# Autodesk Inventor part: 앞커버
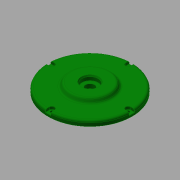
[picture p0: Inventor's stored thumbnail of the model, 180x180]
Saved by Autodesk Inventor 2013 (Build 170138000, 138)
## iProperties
Created: 2016-11
Part Number: 앞커버
Material: 일반
Document SubType Name: Modeling
Designer: mduedu
Density: 2.71 g/cm^3
Mass: 511.35 g
Surface Area: 365.029 cm^2
Volume: 188.69 cm^3
Author: mduedu
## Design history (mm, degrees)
sketch "스케치1"
  geometry: L1 (22, -12.5)-(22, -30); L2 (22, -30)-(16, -33.464); L3 (16, -33.464)-(16, -65); L4 (16, -65)-(8, -65); L5 (8, -65)-(8, -53); L6 (8, -53)-(0, -53); L7 (0, -53)-(0, -14); L8 (0, 0)-(22, 0); L9 (8, -14)-(8, -7); L10 (8, -7)-(14.5, -7); L11 (14.5, -7)-(14.5, -12.5); L12 (0, -14)-(8, -14); L13 (14.5, -12.5)-(22, -12.5)
  constraints: 26 end point, 8 parallel, 3 perpendicular, 2 horizontal, 2 vertical alignment, 1 collinear
  dimensions: "d0" = 8 distance of L5.end L6.end; "d2" = 8 distance of L3.end L4.end; "d3" = 6 distance between parallel lines of L1 L3; "d4" = 120 deg angle of L3 L2; "d5" = 7.5 distance of L11.end L1.start; "d6" = 60 diameter of L1.end L8; "d7" = 14 diameter of L10 L8; "d8" = 28 diameter of L12 L8; "d9" = 25 diameter of L13 L8; "d10" = 106 diameter of L6 L8; "d11" = 130 diameter of L4 L8
revolve "회전1" sketch "스케치1" stored, may be unused: angle "d12" = 90 deg
fillet "모깎기1" dims "d13" = 0.3
fillet "모깎기2" dims "d14" = 3
chamfer "모따기1" distance "d15" = 1; stored, may be unused: second distance "d16" = 2, angle "d17" = 45 deg
fillet "모깎기3" dims "d18" = 0.3
chamfer "모따기2" distance "d36" = 2; stored, may be unused: second distance "d37" = 2, angle "d38" = 30 deg
sketch "스케치3"
  geometry: C1 r 65 at (0, 0) reference; A1 r 59 centre (0, 0) between (0, 59) and (59, 0); 2 further points
  constraints: 4 point on circle, 2 horizontal alignment, 2 vertical alignment, 1 centre point, 1 coincident
  dimensions: "d33" = 118 diameter of A1
sketch "스케치4"
  geometry: 4 further points
  constraints: 4 other
hole "구멍2" sketch "스케치4" at (0, 59), (-59, 0), (59, 0), (0, -59) diameter "d39" = 4.5; stored, may be unused: countersink angle "d43" = 90 deg, drill point angle "d45" = 0 deg; dims "d40" = 6, "d41" = 8, "d42" = 4.6, "d44" = 8
sketch "스케치6"
  geometry: L1 (-4, 5.877)-(-4, 0); L2 (4, 5.877)-(4, 0); A1 r 4 centre (0, 0) between (-2.712, 2.941) and (2.712, 2.941) reference; A2 r 65 centre (0, -59) between (-4, 5.877) and (4, 5.877) reference; 1 further point
  constraints: 4 end point, 4 point on circle, 2 tangent, 2 vertical
extrude "돌출2" cut sketch "스케치6" stored distance "d51" = 10; taper "d52" = 0 deg
fillet "모깎기5" dims "d56" = 0.3
fillet "모깎기6" dims "d57" = 0.3
sketch "스케치5"
  geometry: C1 r 22 at (0, 0); C2 r 45 at (0, 0); 1 further point
  constraints: 2 centre point, 2 coincident
  dimensions: "d46" = 44 diameter of C1; "d47" = 90 diameter of C2
extrude "돌출1" cut sketch "스케치5" distance "d48" = 8; taper "d49" = 0 deg
fillet "모깎기4" dims "d50" = 3
node "솔리드1"
pattern_circular "원형 패턴1" dims angle "d54" = 360 deg
pattern_circular "원형 패턴2" dims angle "d59" = 360 deg
pattern_circular "원형 패턴3" dims angle "d62" = 360 deg
